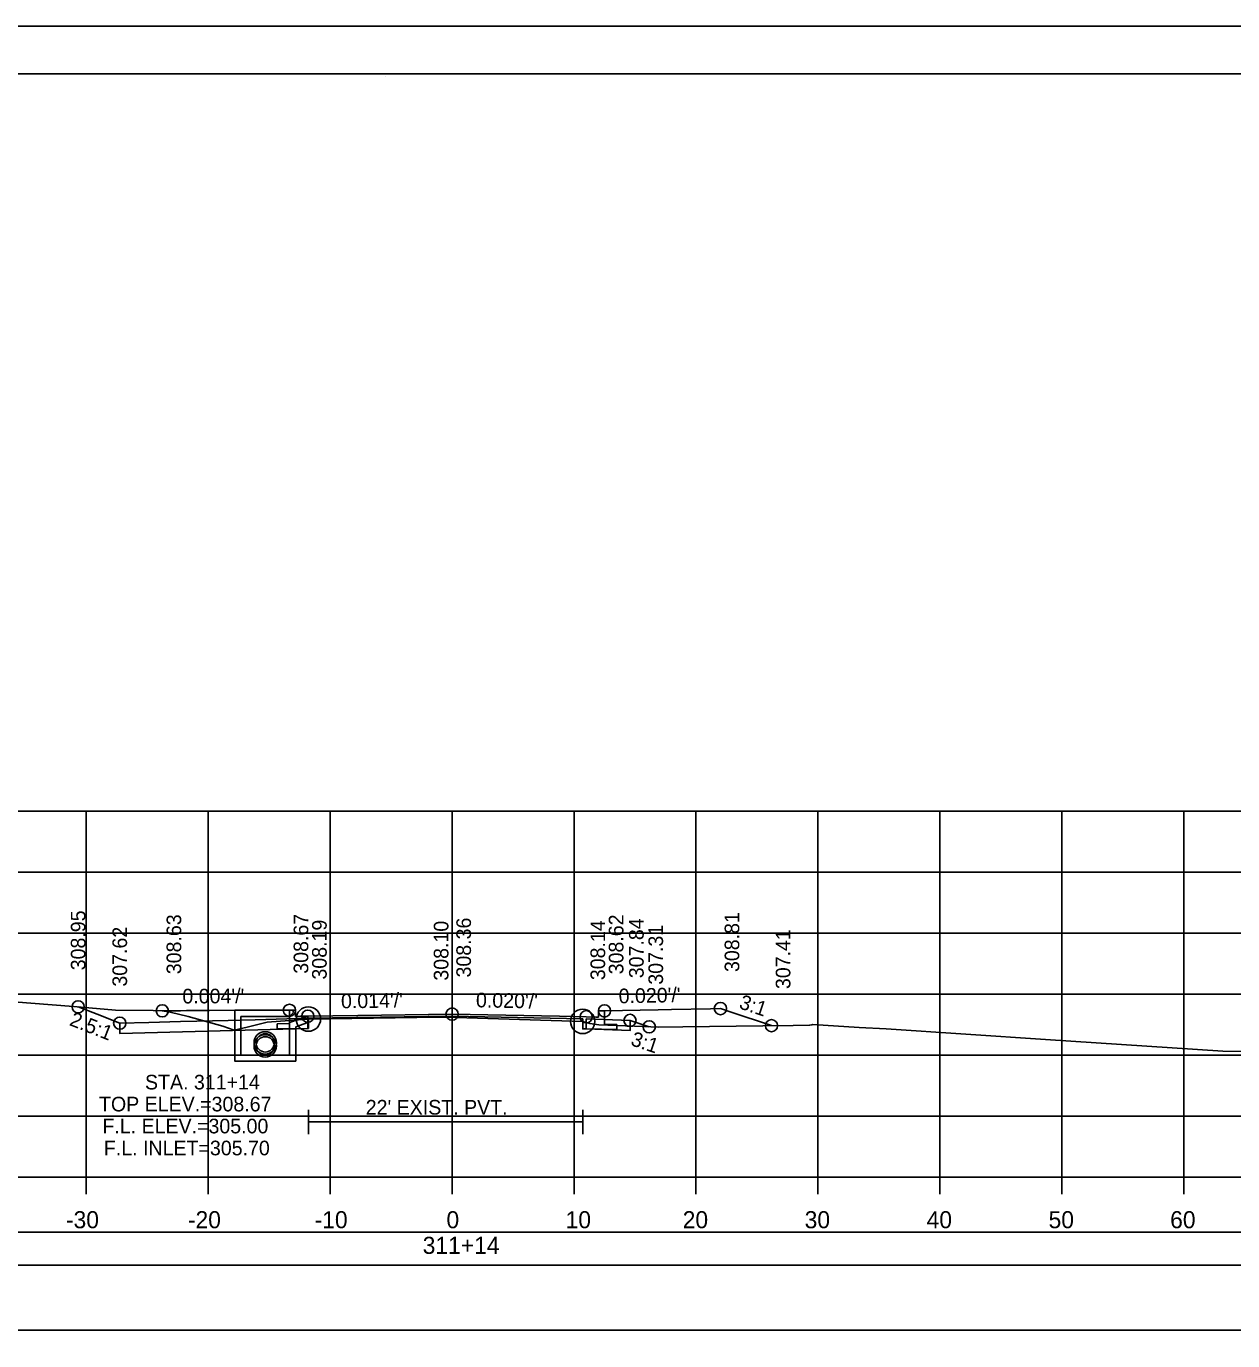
# Model space of a CAD drawing. Extents: x 1370538 to 1372872, y 376220 to 381127.
# Drawn here: x 1370673.7 to 1370772.6, y 378169.8 to 378277.5 of the extents above; entities that cross this region are included whole.
import ezdxf

# ---------------------------------------------------------------- set-up
doc = ezdxf.new("R2010")
doc.units = 0
for name, color, linetype in [('R_Border', 7, 'Continuous'), ('R_Border Notes', 7, 'Continuous'), ('R_Border PE', 7, 'Continuous'), ('R_Border Prem', 7, 'Continuous'), ('R_Dimension', 7, 'Continuous'), ('R_Fin Surface', 7, 'Continuous'), ('R_Grid', 7, 'Continuous'), ('R_Horz Alg Annot', 7, 'Continuous'), ('R_No Plot', 7, 'Continuous'), ('R_Water', 7, 'Continuous'), ('R_Water Annot', 7, 'Continuous'), ('R_Xsect Elev', 7, 'Continuous'), ('R_Xsect Slope', 7, 'Continuous')]:
    doc.layers.add(name, color=color, linetype=linetype)

msp = doc.modelspace()

# ---------------------------------------------------------------- linework, layer by layer
at = {"layer": 'R_Border'}
for p, q in [((1370696.83, 378188.71), (1370696.83, 378186.71)), ((1370719.32, 378188.71), (1370719.32, 378186.71)), ((1370696.83, 378187.71), (1370719.32, 378187.71))]:
    msp.add_line(p, q, dxfattribs=at)
for points in [[(1370708.61, 378196.38), (1370696.83, 378196.21), (1370696.83, 378195.38), (1370696.79, 378195.38), (1370694.27, 378195.33), (1370694.27, 378195.75), (1370695.28, 378195.77), (1370695.28, 378196.86)], [(1370721.11, 378196.81), (1370721.11, 378195.71), (1370722.11, 378195.69), (1370722.11, 378195.28), (1370719.61, 378195.33), (1370719.32, 378195.33), (1370719.32, 378196.16), (1370708.61, 378196.38)]]:
    msp.add_lwpolyline(points, dxfattribs=at)
at = {"layer": 'R_Border Notes'}
for p, q in [((1370550.61, 378273.65), (1370866.79, 378273.65)), ((1370703.13, 378273.39), (1370703.13, 378273.39)), ((1370703.13, 378273.39), (1370703.13, 378273.39))]:
    msp.add_line(p, q, dxfattribs=at)
at = {"layer": 'R_Border Prem'}
for p, q in [((1370558.61, 378183.19), (1370858.61, 378183.19)), ((1370678.61, 378181.79), (1370678.61, 378183.19)), ((1370688.61, 378181.79), (1370688.61, 378183.19)), ((1370698.61, 378181.79), (1370698.61, 378183.19)), ((1370708.61, 378181.79), (1370708.61, 378183.19)), ((1370718.61, 378181.79), (1370718.61, 378183.19)), ((1370728.61, 378181.79), (1370728.61, 378183.19)), ((1370738.61, 378181.79), (1370738.61, 378183.19)), ((1370748.61, 378181.79), (1370748.61, 378183.19)), ((1370758.61, 378181.79), (1370758.61, 378183.19)), ((1370768.61, 378181.79), (1370768.61, 378183.19))]:
    msp.add_line(p, q, dxfattribs=at)
at = {"layer": 'R_Dimension'}
msp.add_lwpolyline([(1370670.91, 378197.7), (1370677.56, 378197.18), (1370681, 378196.88), (1370684.1, 378196.83), (1370684.85, 378196.82), (1370685.5, 378196.7), (1370686.98, 378196.35), (1370689.8, 378195.55), (1370690.74, 378195.23), (1370691.81, 378195.49), (1370693.45, 378195.88), (1370696.02, 378196.08), (1370696.83, 378196.14), (1370707.5, 378196.29), (1370708.36, 378196.3), (1370709.82, 378196.25), (1370719.32, 378195.95), (1370719.91, 378195.78), (1370720.64, 378195.68), (1370724.3, 378195.52), (1370725.51, 378195.47), (1370727.52, 378195.5), (1370734.1, 378195.59), (1370736.59, 378195.61), (1370737.93, 378195.64), (1370738.11, 378195.67), (1370738.2, 378195.7), (1370742, 378195.46), (1370744.21, 378195.33), (1370757.26, 378194.46), (1370771.81, 378193.51), (1370785.72, 378193.44)], dxfattribs=at)
at = {"layer": 'R_Fin Surface'}
for points in [[(1370684.85, 378196.82), (1370686.35, 378196.82), (1370686.83, 378196.83), (1370688.73, 378196.84), (1370695.27, 378196.86), (1370695.56, 378196.86), (1370695.78, 378196.86), (1370695.78, 378196.57), (1370695.78, 378196.36), (1370696.17, 378196.37), (1370696.78, 378196.38), (1370700.87, 378196.43), (1370708.61, 378196.55)], [(1370708.61, 378196.55), (1370717.41, 378196.37), (1370719.61, 378196.33), (1370720.41, 378196.31), (1370720.61, 378196.31), (1370720.61, 378196.71), (1370720.61, 378196.81), (1370720.71, 378196.81), (1370721.11, 378196.81), (1370725.51, 378196.9), (1370726.61, 378196.92), (1370729.81, 378196.98), (1370730.61, 378197), (1370731.41, 378196.73), (1370734.8, 378195.6)]]:
    msp.add_lwpolyline(points, dxfattribs=at)
at = {"layer": 'R_Grid'}
for p, q in [((1370558.61, 378213.19), (1370858.61, 378213.19)), ((1370678.61, 378183.19), (1370678.61, 378213.19)), ((1370688.61, 378183.19), (1370688.61, 378213.19)), ((1370698.61, 378183.19), (1370698.61, 378213.19)), ((1370708.61, 378183.19), (1370708.61, 378213.19)), ((1370718.61, 378183.19), (1370718.61, 378213.19)), ((1370728.61, 378183.19), (1370728.61, 378213.19)), ((1370738.61, 378183.19), (1370738.61, 378213.19)), ((1370748.61, 378183.19), (1370748.61, 378213.19)), ((1370758.61, 378183.19), (1370758.61, 378213.19)), ((1370768.61, 378183.19), (1370768.61, 378213.19)), ((1370558.61, 378208.19), (1370858.61, 378208.19)), ((1370558.61, 378203.19), (1370858.61, 378203.19)), ((1370558.61, 378198.19), (1370858.61, 378198.19)), ((1370558.61, 378193.19), (1370858.61, 378193.19)), ((1370558.61, 378188.19), (1370858.61, 378188.19)), ((1370558.61, 378183.19), (1370858.61, 378183.19))]:
    msp.add_line(p, q, dxfattribs=at)
at = {"layer": 'R_Horz Alg Annot'}
for points in [[(1370677.95, 378197.14), (1370679.5, 378196.53), (1370681.36, 378195.8), (1370683.75, 378195.86), (1370686.35, 378195.93), (1370687.67, 378195.96), (1370690.26, 378196.02), (1370691.28, 378196.05), (1370692.47, 378196.08), (1370696.79, 378196.21)], [(1370696.79, 378196.21), (1370696.79, 378195.38), (1370681.36, 378194.97), (1370681.36, 378195.8)], [(1370719.61, 378196.16), (1370723.2, 378196.03), (1370724.78, 378195.5)], [(1370719.61, 378196.16), (1370719.61, 378195.33), (1370723.2, 378195.2), (1370723.2, 378196.03)]]:
    msp.add_lwpolyline(points, dxfattribs=at)
for points in [[(1370551.13, 378175.95), (1370866.25, 378175.95), (1370866.25, 378178.66), (1370551.13, 378178.66)], [(1370551.13, 378170.63), (1370866.25, 378170.63), (1370866.25, 378175.95), (1370551.13, 378175.95)]]:
    msp.add_lwpolyline(points, close=True, dxfattribs=at)
at = {"layer": 'R_No Plot'}
msp.add_line((1370538.21, 378277.54), (1370871.54, 378277.54), dxfattribs=at)
for points in [[(1370538.2, 378277.54), (1370871.54, 378277.54), (1370871.54, 378064.2), (1370538.2, 378064.2)], [(1370784.53, 378273.65), (1370784.53, 378263.77), (1370820.26, 378263.77), (1370820.26, 378260.85), (1370843.46, 378260.85), (1370843.46, 378236.52), (1370866.79, 378236.52), (1370866.79, 378068.19), (1370550.61, 378068.19), (1370550.61, 378273.65)]]:
    msp.add_lwpolyline(points, close=True, dxfattribs=at)
for centre, radius in [((1370677.95, 378197.14), 0.5), ((1370684.85, 378196.82), 0.5), ((1370684.85, 378196.82), 0.5), ((1370695.27, 378196.86), 0.5), ((1370696.83, 378196.14), 1), ((1370696.78, 378196.38), 0.5), ((1370708.61, 378196.55), 0.5), ((1370708.61, 378196.55), 0.5), ((1370719.32, 378195.95), 1), ((1370719.61, 378196.33), 0.5), ((1370721.11, 378196.81), 0.5), ((1370730.61, 378197), 0.5), ((1370681.36, 378195.8), 0.5), ((1370723.2, 378196.03), 0.5), ((1370724.78, 378195.5), 0.5), ((1370734.8, 378195.6), 0.5), ((1370693.29, 378194.19), 0.917), ((1370693.29, 378193.94), 0.917), ((1370693.29, 378193.94), 0.917)]:
    msp.add_circle(centre, radius, dxfattribs=at)
at = {"layer": 'R_Water'}
for p, q in [((1370690.79, 378196.86), (1370695.54, 378196.86)), ((1370690.79, 378195.36), (1370690.79, 378196.86)), ((1370695.62, 378196.69), (1370695.54, 378196.86)), ((1370691.29, 378195.36), (1370691.29, 378196.36)), ((1370691.29, 378196.36), (1370695.29, 378196.36)), ((1370695.62, 378196.69), (1370695.29, 378196.36)), ((1370696.79, 378196.38), (1370695.29, 378195.86)), ((1370695.29, 378195.36), (1370695.29, 378195.86)), ((1370696.79, 378195.85), (1370695.79, 378195.5)), ((1370695.79, 378195.36), (1370695.79, 378195.5))]:
    msp.add_line(p, q, dxfattribs=at)
for points in [[(1370696.79, 378195.85), (1370696.79, 378196.38)], [(1370695.79, 378195.36), (1370695.79, 378192.69), (1370693.29, 378192.69), (1370690.79, 378192.69), (1370690.79, 378195.36)], [(1370695.29, 378195.36), (1370695.29, 378193.19), (1370693.29, 378193.19), (1370691.29, 378193.19), (1370691.29, 378195.36)]]:
    msp.add_lwpolyline(points, dxfattribs=at)
for centre in [(1370693.29, 378194.19), (1370693.29, 378193.94), (1370693.29, 378193.94)]:
    msp.add_circle(centre, 0.75, dxfattribs=at)
at = {"layer": 'R_Xsect Elev'}
msp.add_line((1370708.61, 378196.29), (1370708.61, 378206.29), dxfattribs=at)

# ---------------------------------------------------------------- texts
at = {"layer": 'R_Border PE'}
for s, p in [('-30', (1370676.95, 378178.99)), ('-20', (1370686.95, 378178.99)), ('-10', (1370697.34, 378178.99)), ('0', (1370708.15, 378178.99)), ('10', (1370717.92, 378178.99)), ('20', (1370727.52, 378178.99)), ('30', (1370737.52, 378178.99)), ('40', (1370747.52, 378178.99)), ('50', (1370757.52, 378178.99)), ('60', (1370767.49, 378178.99)), ('311+14', (1370706.2, 378176.89))]:
    msp.add_text(s, height=1.4, dxfattribs=at).set_placement(p)
at = {"layer": 'R_Water'}
msp.add_text("22' EXIST. PVT.", height=1.2, dxfattribs=at).set_placement((1370701.53, 378188.31))
at = {"layer": 'R_Water Annot'}
for s, p in [('STA. 311+14', (1370683.43, 378190.37)), ('TOP ELEV.=308.67', (1370679.66, 378188.57)), ('F.L. ELEV.=305.00', (1370679.94, 378186.77)), ('F.L. INLET=305.70', (1370680.06, 378184.97))]:
    msp.add_text(s, height=1.2, dxfattribs=at).set_placement(p)
at = {"layer": 'R_Xsect Elev'}
for s, p in [('308.95', (1370678.55, 378200.14)), ('308.63', (1370686.4, 378199.82)), ('308.63', (1370686.4, 378199.82)), ('308.67', (1370696.82, 378199.86)), ('308.36', (1370710.16, 378199.55)), ('308.62', (1370722.66, 378199.81)), ('307.84', (1370724.32, 378199.49)), ('308.81', (1370732.16, 378200)), ('307.62', (1370681.96, 378198.8)), ('308.19', (1370698.33, 378199.38)), ('308.10', (1370708.31, 378199.29)), ('308.14', (1370721.16, 378199.33)), ('307.31', (1370725.91, 378198.96)), ('307.41', (1370736.35, 378198.6))]:
    msp.add_text(s, height=1.2, rotation=90, dxfattribs=at).set_placement(p)
at = {"layer": 'R_Xsect Slope'}
for s, rotation, p in [("0.004'/'", 0.2358, (1370686.5, 378197.42)), ("0.014'/'", 0.8199, (1370699.51, 378197.02)), ("0.020'/'", 358.8542, (1370710.56, 378197.11)), ("0.020'/'", 1.1458, (1370722.28, 378197.43)), ('3:1', 341.5651, (1370732.07, 378197.04)), ('2.5:1', 338.5667, (1370677.16, 378195.66)), ('3:1', 341.5668, (1370723.18, 378194.02))]:
    msp.add_text(s, height=1.2, rotation=rotation, dxfattribs=at).set_placement(p)

doc.saveas('drawing.dxf')
